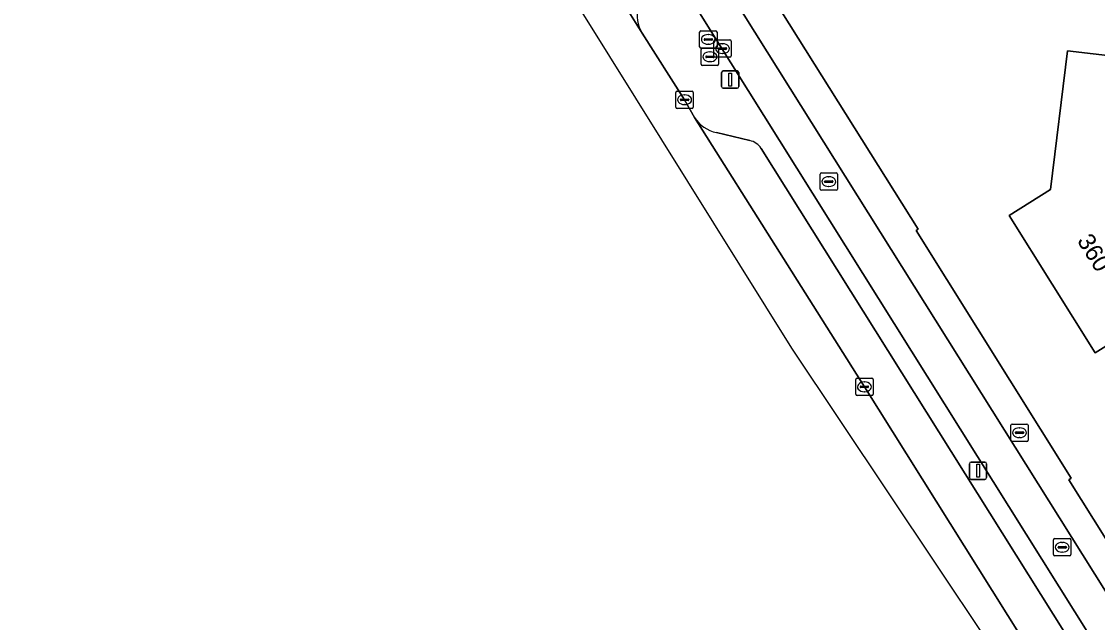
# Model space of a CAD drawing. Extents: x 160023 to 161302, y 384750 to 385707.
# Drawn here: x 160088 to 160150, y 385120.4 to 385155 of the extents above; entities that cross this region are included whole.
import ezdxf

# ---------------------------------------------------------------- set-up
doc = ezdxf.new("R2010")
doc.units = 0
for name, color, linetype in [('IMGEO_Berm_open', 7, 'Continuous'), ('IMGEO_Brandkraan', 7, 'Continuous'), ('IMGEO_Erf', 7, 'Continuous'), ('IMGEO_Fietspad_gesloten', 7, 'Continuous'), ('IMGEO_Kolk', 7, 'Continuous'), ('IMGEO_Lichtmast', 7, 'Continuous'), ('IMGEO_Pand', 7, 'Continuous'), ('IMGEO_Pand_nummerreeks', 7, 'Continuous'), ('IMGEO_Parkeervlak_open', 7, 'Continuous'), ('IMGEO_Rijbaan_regionaal_gesloten', 7, 'Continuous'), ('IMGEO_Rioolput', 7, 'Continuous'), ('IMGEO_Voetpad_open', 7, 'Continuous')]:
    doc.layers.add(name, color=color, linetype=linetype)

msp = doc.modelspace()

# ---------------------------------------------------------------- linework, layer by layer
at = {"layer": 'IMGEO_Berm_open'}
for points in [[(160150.574, 385117.95), (160124.152, 385160.161), (160085.578, 385221.627), (160067.835, 385250), (160061.871, 385259.541), (160032.543, 385306.417)], [(160123.75, 385154.328), (160126.191, 385150.495), (160126.752, 385149.483)], [(160128.025, 385148.6), (160129.95, 385148.147)], [(160130.602, 385147.694), (160149.652, 385117.292)]]:
    msp.add_lwpolyline(points, dxfattribs=at)
for centre, radius, start, end in [((160125.624, 385155.432), 2.175, 168.95897, 210.515), ((160128.513, 385150.663), 2.12, 213.81983, 256.68695), ((160129.716, 385147.115), 1.058, 33.18315, 77.23485)]:
    msp.add_arc(centre, radius, start, end, dxfattribs=at)
at = {"layer": 'IMGEO_Brandkraan'}
for p, q in [((160144.98, 385130.883), (160144.98, 385131.735)), ((160145.055, 385131.809), (160145.907, 385131.809)), ((160145.981, 385131.735), (160145.981, 385130.883)), ((160145.239, 385131.303), (160145.239, 385131.315)), ((160145.677, 385131.266), (160145.279, 385131.266)), ((160145.282, 385131.352), (160145.68, 385131.352)), ((160145.468, 385131.589), (160145.493, 385131.589)), ((160145.723, 385131.315), (160145.723, 385131.303)), ((160145.907, 385130.809), (160145.055, 385130.809)), ((160145.491, 385131.029), (160145.466, 385131.029))]:
    msp.add_line(p, q, dxfattribs=at)
for points in [[(160144.98, 385130.883), (160144.98, 385131.735)], [(160145.055, 385131.809), (160145.907, 385131.809)], [(160145.981, 385131.735), (160145.981, 385130.883)], [(160145.907, 385130.809), (160145.055, 385130.809)]]:
    msp.add_lwpolyline(points, dxfattribs=at)
for centre, radius, start, end in [((160145.057, 385131.733), 0.0765, 91.55205, 178.44795), ((160145.057, 385131.733), 0.0765, 91.55205, 178.44795), ((160145.905, 385131.733), 0.0765, 1.55205, 88.44795), ((160145.905, 385131.733), 0.0765, 1.55205, 88.44795), ((160145.279, 385131.312), 0.0403, 85.87752, 175.75265), ((160145.276, 385131.302), 0.0366, 178.93798, 274.71019), ((160145.68, 385131.309), 0.043, 264.86636, 352.45326), ((160145.684, 385131.314), 0.0386, 1.73085, 96.63898), ((160145.057, 385130.885), 0.0765, 181.55205, 268.44795), ((160145.057, 385130.885), 0.0765, 181.55205, 268.44795), ((160145.905, 385130.885), 0.0765, 271.55205, 358.44795), ((160145.905, 385130.885), 0.0765, 271.55205, 358.44795)]:
    msp.add_arc(centre, radius, start, end, dxfattribs=at)
for centre, major_axis, ratio, start_param, end_param in [((160145.467, 385131.309), (-0.387, 0.002), 0.722429, 4.712389, 7.853982), ((160145.492, 385131.309), (-0.39, 0.002), 0.717154, 1.570796, 4.712389)]:
    msp.add_ellipse(centre, major_axis=major_axis, ratio=ratio, start_param=start_param, end_param=end_param, dxfattribs=at)
at = {"layer": 'IMGEO_Erf'}
for points in [[(160163.285, 385173.33), (160162.52, 385172.217), (160162.431, 385172.087), (160149.11, 385166.984), (160148.183, 385166.713), (160144.1, 385165.517), (160143.718, 385165.332), (160143.55, 385165.613), (160142.997, 385165.45), (160143.216, 385165.089), (160144.602, 385162.798), (160141.098, 385160.677), (160139.545, 385163.243), (160132.29, 385158.902), (160131.796, 385155.539), (160139.639, 385143.033), (160139.521, 385142.959), (160148.446, 385128.686), (160148.312, 385128.594), (160154.705, 385118.402), (160155.002, 385118.237), (160155.05, 385118.556), (160155.505, 385121.584), (160162.866, 385170.546)], [(160148.247, 385153.311), (160154.983, 385152.521), (160154.594, 385149.645), (160157.809, 385144.504), (160155.462, 385143.037), (160157.086, 385140.44), (160149.835, 385135.907), (160144.881, 385143.83), (160147.264, 385145.32)]]:
    msp.add_lwpolyline(points, close=True, dxfattribs=at)
at = {"layer": 'IMGEO_Fietspad_gesloten'}
msp.add_lwpolyline([(160026.031, 385317.314), (160026.044, 385317.29), (160028.006, 385313.738), (160028.321, 385313.156), (160030.444, 385309.783), (160032.543, 385306.417), (160061.871, 385259.541), (160067.835, 385250), (160085.578, 385221.627), (160124.152, 385160.161), (160150.574, 385117.95), (160168.154, 385089.798), (160170.064, 385090.861), (160169.92, 385091.091), (160127.678, 385158.489), (160123.778, 385164.743), (160087.491, 385222.641), (160070.35, 385250), (160030.703, 385313.283), (160030.2, 385314.143), (160029.339, 385315.616), (160028.117, 385317.706), (160027.3, 385319.103), (160027.281, 385319.136)], close=True, dxfattribs=at)
at = {"layer": 'IMGEO_Kolk'}
for p, q in [((160125.691, 385150.07), (160125.691, 385150.922)), ((160125.766, 385150.996), (160126.618, 385150.996)), ((160126.692, 385150.922), (160126.692, 385150.07)), ((160125.95, 385150.49), (160125.95, 385150.502)), ((160126.388, 385150.453), (160125.99, 385150.453)), ((160125.993, 385150.539), (160126.391, 385150.539)), ((160126.179, 385150.776), (160126.204, 385150.776)), ((160126.434, 385150.502), (160126.434, 385150.49)), ((160126.618, 385149.996), (160125.766, 385149.996)), ((160126.202, 385150.216), (160126.177, 385150.216)), ((160136.045, 385133.528), (160136.045, 385134.38)), ((160136.12, 385134.454), (160136.972, 385134.454)), ((160136.533, 385134.234), (160136.558, 385134.234)), ((160137.046, 385134.38), (160137.046, 385133.528)), ((160136.304, 385133.948), (160136.304, 385133.96)), ((160136.742, 385133.911), (160136.344, 385133.911)), ((160136.347, 385133.997), (160136.745, 385133.997)), ((160136.556, 385133.674), (160136.531, 385133.674)), ((160136.788, 385133.96), (160136.788, 385133.948)), ((160136.972, 385133.454), (160136.12, 385133.454))]:
    msp.add_line(p, q, dxfattribs=at)
for points in [[(160125.691, 385150.07), (160125.691, 385150.922)], [(160125.766, 385150.996), (160126.618, 385150.996)], [(160126.692, 385150.922), (160126.692, 385150.07)], [(160126.618, 385149.996), (160125.766, 385149.996)], [(160136.045, 385133.528), (160136.045, 385134.38)], [(160136.12, 385134.454), (160136.972, 385134.454)], [(160137.046, 385134.38), (160137.046, 385133.528)], [(160136.972, 385133.454), (160136.12, 385133.454)]]:
    msp.add_lwpolyline(points, dxfattribs=at)
for centre, radius, start, end in [((160125.768, 385150.92), 0.0765, 91.55205, 178.44795), ((160125.768, 385150.92), 0.0765, 91.55205, 178.44795), ((160126.616, 385150.92), 0.0765, 1.55205, 88.44795), ((160126.616, 385150.92), 0.0765, 1.55205, 88.44795), ((160125.99, 385150.499), 0.0403, 85.87752, 175.75265), ((160125.987, 385150.489), 0.0366, 178.93798, 274.71019), ((160126.391, 385150.496), 0.043, 264.86636, 352.45326), ((160126.395, 385150.501), 0.0386, 1.73085, 96.63898), ((160125.768, 385150.072), 0.0765, 181.55205, 268.44795), ((160125.768, 385150.072), 0.0765, 181.55205, 268.44795), ((160126.616, 385150.072), 0.0765, 271.55205, 358.44795), ((160126.616, 385150.072), 0.0765, 271.55205, 358.44795), ((160136.122, 385134.378), 0.0765, 91.55205, 178.44795), ((160136.122, 385134.378), 0.0765, 91.55205, 178.44795), ((160136.97, 385134.378), 0.0765, 1.55205, 88.44795), ((160136.97, 385134.378), 0.0765, 1.55205, 88.44795), ((160136.344, 385133.957), 0.0403, 85.87752, 175.75265), ((160136.341, 385133.947), 0.0366, 178.93798, 274.71019), ((160136.745, 385133.954), 0.043, 264.86636, 352.45326), ((160136.749, 385133.959), 0.0386, 1.73085, 96.63898), ((160136.122, 385133.53), 0.0765, 181.55205, 268.44795), ((160136.122, 385133.53), 0.0765, 181.55205, 268.44795), ((160136.97, 385133.53), 0.0765, 271.55205, 358.44795), ((160136.97, 385133.53), 0.0765, 271.55205, 358.44795)]:
    msp.add_arc(centre, radius, start, end, dxfattribs=at)
for centre, major_axis, ratio, start_param, end_param in [((160126.178, 385150.496), (-0.387, 0.002), 0.722429, 4.712389, 7.853982), ((160126.203, 385150.496), (-0.39, 0.002), 0.717154, 1.570796, 4.712389), ((160136.532, 385133.954), (-0.387, 0.002), 0.722429, 4.712389, 7.853982), ((160136.557, 385133.954), (-0.39, 0.002), 0.717154, 1.570796, 4.712389)]:
    msp.add_ellipse(centre, major_axis=major_axis, ratio=ratio, start_param=start_param, end_param=end_param, dxfattribs=at)
at = {"layer": 'IMGEO_Lichtmast'}
for p, q in [((160128.42, 385152.16), (160129.21, 385152.16)), ((160129.21, 385152.16), (160128.42, 385152.16)), ((160128.32, 385151.26), (160128.32, 385152.06)), ((160128.32, 385152.06), (160128.32, 385151.26)), ((160129.31, 385152.06), (160129.31, 385151.26)), ((160129.31, 385151.26), (160129.31, 385152.06)), ((160129.21, 385151.16), (160128.42, 385151.16)), ((160128.42, 385151.16), (160129.21, 385151.16)), ((160142.597, 385128.721), (160142.597, 385129.521)), ((160142.597, 385129.521), (160142.597, 385128.721)), ((160142.697, 385129.621), (160143.487, 385129.621)), ((160143.487, 385129.621), (160142.697, 385129.621)), ((160143.587, 385129.521), (160143.587, 385128.721)), ((160143.587, 385128.721), (160143.587, 385129.521)), ((160143.487, 385128.621), (160142.697, 385128.621)), ((160142.697, 385128.621), (160143.487, 385128.621))]:
    msp.add_line(p, q, dxfattribs=at)
for points in [[(160128.74, 385152.035), (160128.89, 385152.035), (160128.89, 385151.285), (160128.74, 385151.285), (160128.74, 385152.035)], [(160143.017, 385129.496), (160143.167, 385129.496), (160143.167, 385128.746), (160143.017, 385128.746), (160143.017, 385129.496)]]:
    msp.add_lwpolyline(points, dxfattribs=at)
for centre, start, end in [((160128.42, 385152.06), 90, 180), ((160128.42, 385152.06), 90, 180), ((160129.21, 385152.06), 0, 90), ((160129.21, 385152.06), 360, 90), ((160128.42, 385151.26), 180, 270), ((160128.42, 385151.26), 180, 270), ((160129.21, 385151.26), 270, 0), ((160129.21, 385151.26), 270, 0), ((160142.697, 385129.521), 90, 180), ((160142.697, 385129.521), 90, 180), ((160143.487, 385129.521), 0, 90), ((160143.487, 385129.521), 360, 90), ((160142.697, 385128.721), 180, 270), ((160142.697, 385128.721), 180, 270), ((160143.487, 385128.721), 270, 0), ((160143.487, 385128.721), 270, 0)]:
    msp.add_arc(centre, 0.1, start, end, dxfattribs=at)
at = {"layer": 'IMGEO_Pand'}
msp.add_lwpolyline([(160157.086, 385140.44), (160155.462, 385143.037), (160157.809, 385144.504), (160154.594, 385149.645), (160154.983, 385152.521), (160148.247, 385153.311), (160147.264, 385145.32), (160144.881, 385143.83), (160149.835, 385135.907)], close=True, dxfattribs=at)
at = {"layer": 'IMGEO_Parkeervlak_open'}
for points in [[(160036.648, 385293.448), (160037.977, 385291.321), (160044.011, 385281.7), (160048.487, 385274.563), (160059.264, 385257.412), (160064.086, 385250), (160070.748, 385239.76), (160081.666, 385221.573), (160092.507, 385204.256), (160103.411, 385186.881), (160114.434, 385169.251), (160123.75, 385154.328)], [(160126.752, 385149.483), (160136.545, 385133.954), (160147.221, 385116.919), (160149.595, 385113.116)], [(160129.95, 385148.147), (160128.025, 385148.6)], [(160149.652, 385117.292), (160130.602, 385147.694)]]:
    msp.add_lwpolyline(points, dxfattribs=at)
for centre, radius, start, end in [((160125.624, 385155.432), 2.175, 168.95897, 210.515), ((160128.513, 385150.663), 2.12, 213.81983, 256.68695), ((160129.716, 385147.115), 1.058, 33.18315, 77.23485)]:
    msp.add_arc(centre, radius, start, end, dxfattribs=at)
at = {"layer": 'IMGEO_Rijbaan_regionaal_gesloten'}
msp.add_lwpolyline([(160147.221, 385116.919), (160136.545, 385133.954), (160126.752, 385149.483), (160126.191, 385150.495), (160123.75, 385154.328), (160114.434, 385169.251), (160103.411, 385186.881), (160092.507, 385204.256), (160081.666, 385221.573), (160070.748, 385239.76), (160064.086, 385250), (160059.264, 385257.412), (160048.487, 385274.563), (160044.011, 385281.7), (160037.977, 385291.321), (160036.648, 385293.448), (160033.754, 385294.437), (160038.311, 385287.118), (160087.33, 385208.396), (160132.353, 385136.178), (160151.876, 385106.938)], dxfattribs=at)
at = {"layer": 'IMGEO_Rioolput'}
for p, q in [((160127.056, 385153.546), (160127.056, 385154.398)), ((160127.131, 385154.472), (160127.983, 385154.472)), ((160127.358, 385154.015), (160127.756, 385154.015)), ((160127.544, 385154.252), (160127.569, 385154.252)), ((160128.057, 385154.398), (160128.057, 385153.546)), ((160127.983, 385153.472), (160127.131, 385153.472)), ((160127.149, 385152.547), (160127.149, 385153.399)), ((160127.224, 385153.473), (160128.076, 385153.473)), ((160127.315, 385153.966), (160127.315, 385153.978)), ((160127.753, 385153.929), (160127.355, 385153.929)), ((160127.567, 385153.692), (160127.542, 385153.692)), ((160127.799, 385153.978), (160127.799, 385153.966)), ((160127.868, 385153.019), (160127.868, 385153.871)), ((160127.943, 385153.945), (160128.795, 385153.945)), ((160128.127, 385153.439), (160128.127, 385153.451)), ((160128.15, 385153.399), (160128.15, 385152.547)), ((160128.565, 385153.402), (160128.167, 385153.402)), ((160128.17, 385153.488), (160128.568, 385153.488)), ((160128.356, 385153.725), (160128.381, 385153.725)), ((160128.611, 385153.451), (160128.611, 385153.439)), ((160128.869, 385153.871), (160128.869, 385153.019)), ((160127.408, 385152.967), (160127.408, 385152.979)), ((160127.846, 385152.93), (160127.448, 385152.93)), ((160127.451, 385153.016), (160127.849, 385153.016)), ((160127.637, 385153.253), (160127.662, 385153.253)), ((160127.892, 385152.979), (160127.892, 385152.967)), ((160128.795, 385152.945), (160127.943, 385152.945)), ((160128.379, 385153.165), (160128.354, 385153.165)), ((160128.076, 385152.473), (160127.224, 385152.473)), ((160127.66, 385152.693), (160127.635, 385152.693)), ((160133.993, 385145.352), (160133.993, 385146.204)), ((160134.068, 385146.278), (160134.92, 385146.278)), ((160134.481, 385146.058), (160134.506, 385146.058)), ((160134.994, 385146.204), (160134.994, 385145.352)), ((160134.252, 385145.772), (160134.252, 385145.784)), ((160134.69, 385145.735), (160134.292, 385145.735)), ((160134.295, 385145.821), (160134.693, 385145.821)), ((160134.504, 385145.498), (160134.479, 385145.498)), ((160134.736, 385145.784), (160134.736, 385145.772)), ((160134.92, 385145.278), (160134.068, 385145.278)), ((160147.438, 385124.282), (160147.438, 385125.134)), ((160147.513, 385125.208), (160148.365, 385125.208)), ((160147.926, 385124.988), (160147.951, 385124.988)), ((160148.439, 385125.134), (160148.439, 385124.282)), ((160147.697, 385124.702), (160147.697, 385124.714)), ((160148.135, 385124.665), (160147.737, 385124.665)), ((160147.74, 385124.751), (160148.138, 385124.751)), ((160147.949, 385124.428), (160147.924, 385124.428)), ((160148.181, 385124.714), (160148.181, 385124.702)), ((160148.365, 385124.208), (160147.513, 385124.208))]:
    msp.add_line(p, q, dxfattribs=at)
for points in [[(160127.056, 385153.546), (160127.056, 385154.398)], [(160127.131, 385154.472), (160127.983, 385154.472)], [(160128.057, 385154.398), (160128.057, 385153.546)], [(160127.983, 385153.472), (160127.131, 385153.472)], [(160127.149, 385152.547), (160127.149, 385153.399)], [(160127.224, 385153.473), (160128.076, 385153.473)], [(160127.868, 385153.019), (160127.868, 385153.871)], [(160127.943, 385153.945), (160128.795, 385153.945)], [(160128.15, 385153.399), (160128.15, 385152.547)], [(160128.869, 385153.871), (160128.869, 385153.019)], [(160128.795, 385152.945), (160127.943, 385152.945)], [(160128.076, 385152.473), (160127.224, 385152.473)], [(160133.993, 385145.352), (160133.993, 385146.204)], [(160134.068, 385146.278), (160134.92, 385146.278)], [(160134.994, 385146.204), (160134.994, 385145.352)], [(160134.92, 385145.278), (160134.068, 385145.278)], [(160147.438, 385124.282), (160147.438, 385125.134)], [(160147.513, 385125.208), (160148.365, 385125.208)], [(160148.439, 385125.134), (160148.439, 385124.282)], [(160148.365, 385124.208), (160147.513, 385124.208)]]:
    msp.add_lwpolyline(points, dxfattribs=at)
for centre, radius, start, end in [((160127.133, 385154.396), 0.0765, 91.55205, 178.44795), ((160127.133, 385154.396), 0.0765, 91.55205, 178.44795), ((160127.355, 385153.975), 0.0403, 85.87752, 175.75265), ((160127.76, 385153.977), 0.0386, 1.73085, 96.63898), ((160127.981, 385154.396), 0.0765, 1.55205, 88.44795), ((160127.981, 385154.396), 0.0765, 1.55205, 88.44795), ((160127.133, 385153.548), 0.0765, 181.55205, 268.44795), ((160127.133, 385153.548), 0.0765, 181.55205, 268.44795), ((160127.226, 385153.397), 0.0765, 91.55205, 178.44795), ((160127.226, 385153.397), 0.0765, 91.55205, 178.44795), ((160127.352, 385153.965), 0.0366, 178.93798, 274.71019), ((160127.756, 385153.972), 0.043, 264.86636, 352.45326), ((160127.945, 385153.869), 0.0765, 91.55205, 178.44795), ((160127.945, 385153.869), 0.0765, 91.55205, 178.44795), ((160127.981, 385153.548), 0.0765, 271.55205, 358.44795), ((160127.981, 385153.548), 0.0765, 271.55205, 358.44795), ((160128.074, 385153.397), 0.0765, 1.55205, 88.44795), ((160128.074, 385153.397), 0.0765, 1.55205, 88.44795), ((160128.167, 385153.448), 0.0403, 85.87752, 175.75265), ((160128.164, 385153.438), 0.0366, 178.93798, 274.71019), ((160128.568, 385153.445), 0.043, 264.86636, 352.45326), ((160128.572, 385153.45), 0.0386, 1.73085, 96.63898), ((160128.793, 385153.869), 0.0765, 1.55205, 88.44795), ((160128.793, 385153.869), 0.0765, 1.55205, 88.44795), ((160127.448, 385152.976), 0.0403, 85.87752, 175.75265), ((160127.445, 385152.966), 0.0366, 178.93798, 274.71019), ((160127.849, 385152.973), 0.043, 264.86636, 352.45326), ((160127.853, 385152.978), 0.0386, 1.73085, 96.63898), ((160127.945, 385153.021), 0.0765, 181.55205, 268.44795), ((160127.945, 385153.021), 0.0765, 181.55205, 268.44795), ((160128.793, 385153.021), 0.0765, 271.55205, 358.44795), ((160128.793, 385153.021), 0.0765, 271.55205, 358.44795), ((160127.226, 385152.549), 0.0765, 181.55205, 268.44795), ((160127.226, 385152.549), 0.0765, 181.55205, 268.44795), ((160128.074, 385152.549), 0.0765, 271.55205, 358.44795), ((160128.074, 385152.549), 0.0765, 271.55205, 358.44795), ((160134.07, 385146.202), 0.0765, 91.55205, 178.44795), ((160134.07, 385146.202), 0.0765, 91.55205, 178.44795), ((160134.918, 385146.202), 0.0765, 1.55205, 88.44795), ((160134.918, 385146.202), 0.0765, 1.55205, 88.44795), ((160134.07, 385145.354), 0.0765, 181.55205, 268.44795), ((160134.07, 385145.354), 0.0765, 181.55205, 268.44795), ((160134.292, 385145.781), 0.0403, 85.87752, 175.75265), ((160134.289, 385145.771), 0.0366, 178.93798, 274.71019), ((160134.693, 385145.778), 0.043, 264.86636, 352.45326), ((160134.697, 385145.783), 0.0386, 1.73085, 96.63898), ((160134.918, 385145.354), 0.0765, 271.55205, 358.44795), ((160134.918, 385145.354), 0.0765, 271.55205, 358.44795), ((160147.515, 385125.132), 0.0765, 91.55205, 178.44795), ((160147.515, 385125.132), 0.0765, 91.55205, 178.44795), ((160148.363, 385125.132), 0.0765, 1.55205, 88.44795), ((160148.363, 385125.132), 0.0765, 1.55205, 88.44795), ((160147.515, 385124.284), 0.0765, 181.55205, 268.44795), ((160147.515, 385124.284), 0.0765, 181.55205, 268.44795), ((160147.737, 385124.711), 0.0403, 85.87752, 175.75265), ((160147.734, 385124.701), 0.0366, 178.93798, 274.71019), ((160148.138, 385124.708), 0.043, 264.86636, 352.45326), ((160148.142, 385124.713), 0.0386, 1.73085, 96.63898), ((160148.363, 385124.284), 0.0765, 271.55205, 358.44795), ((160148.363, 385124.284), 0.0765, 271.55205, 358.44795)]:
    msp.add_arc(centre, radius, start, end, dxfattribs=at)
for centre, major_axis, ratio, start_param, end_param in [((160127.543, 385153.972), (-0.387, 0.002), 0.722429, 4.712389, 7.853982), ((160127.568, 385153.972), (-0.39, 0.002), 0.717154, 1.570796, 4.712389), ((160128.355, 385153.445), (-0.387, 0.002), 0.722429, 4.712389, 7.853982), ((160128.38, 385153.445), (-0.39, 0.002), 0.717154, 1.570796, 4.712389), ((160127.636, 385152.973), (-0.387, 0.002), 0.722429, 4.712389, 7.853982), ((160127.661, 385152.973), (-0.39, 0.002), 0.717154, 1.570796, 4.712389), ((160134.48, 385145.778), (-0.387, 0.002), 0.722429, 4.712389, 7.853982), ((160134.505, 385145.778), (-0.39, 0.002), 0.717154, 1.570796, 4.712389), ((160147.925, 385124.708), (-0.387, 0.002), 0.722429, 4.712389, 7.853982), ((160147.95, 385124.708), (-0.39, 0.002), 0.717154, 1.570796, 4.712389)]:
    msp.add_ellipse(centre, major_axis=major_axis, ratio=ratio, start_param=start_param, end_param=end_param, dxfattribs=at)
at = {"layer": 'IMGEO_Voetpad_open'}
for points in [[(160139.521, 385142.959), (160139.639, 385143.033), (160131.796, 385155.539), (160129.077, 385160.445), (160127.998, 385159.808)], [(160127.678, 385158.489), (160169.92, 385091.091), (160170.064, 385090.861), (160171.885, 385091.874), (160155.435, 385118.099), (160155.339, 385118.049), (160155.002, 385118.237), (160154.705, 385118.402), (160148.312, 385128.594), (160148.446, 385128.686), (160139.521, 385142.959)]]:
    msp.add_lwpolyline(points, dxfattribs=at)

# ---------------------------------------------------------------- texts
at = {"layer": 'IMGEO_Pand_nummerreeks'}
msp.add_text('360', height=1, rotation=302.01643, dxfattribs=at).set_placement((160148.766, 385142.371))

doc.saveas('drawing.dxf')
